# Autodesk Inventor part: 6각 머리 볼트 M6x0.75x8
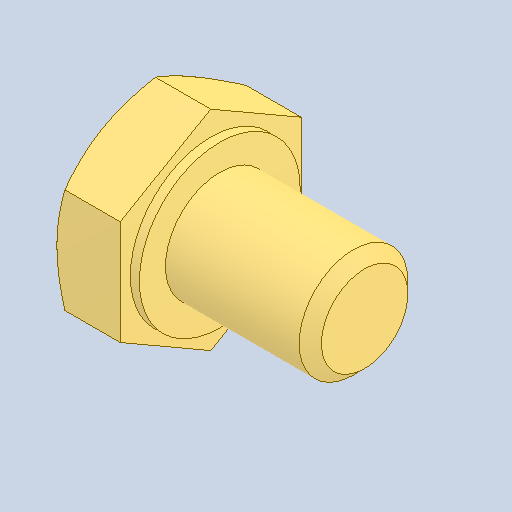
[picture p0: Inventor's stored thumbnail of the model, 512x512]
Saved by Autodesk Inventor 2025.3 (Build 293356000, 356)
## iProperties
Created: 2025-10
Part Number: 6각 머리 볼트 M6x0.75x8
Material: 강철, 연강
Description: 6각 머리 볼트 및 6각 머리 나사
Document SubType Name: Modeling
Designer: USER
Density: 7.85 g/cm^3
Appearance: 기본값
Author: jhkim
Sending System: Autodesk Inventor 2026
Preprocessor: ST-DEVELOPER v20.1
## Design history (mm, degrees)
feature "Solid1"
node "솔리드1"
